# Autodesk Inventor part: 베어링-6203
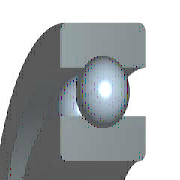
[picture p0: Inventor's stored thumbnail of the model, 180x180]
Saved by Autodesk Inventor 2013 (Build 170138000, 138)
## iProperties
IsCustomPart: 0
Created: 2016-05
Part Number: 베어링-6203
Material: 강철, 연강
Description: 깊은 그루브 볼 베어링
Document SubType Name: Modeling
Standard: KS B 2023
Designer: mduedu
Standards Organization: KS
Language: ko-KR
Size Designation: 6203 - 17 x 40 x 12
Categories: <MemberInstance><Categories><Category DisplayName="샤프트 부품" InternalName="7f7aeb1f-a693-4053-b835-cee3144e0d98" Mnemonic="SHFT"><Category DisplayName="베어링" Inter
Density: 1 g/cm^3
Author: mduedu
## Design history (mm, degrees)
sketch "스케치" dims "d0" = 5.98 (= -0.26 x WD + 0.26 x BD)
  geometry: L1 (3.01, 14.25)-(8.99, 14.25); L2 (6, 14.25)-(6, 11.26); L3 (6, 14.25)-(6, 17.24); L4 (3.778, 12.249)-(0, 12.249); L5 (0, 8.5)-(12, 8.5); L6 (3.778, 16.251)-(0, 16.251); L7 (0, 20)-(12, 20); L8 (12, 8.5)-(12, 12.249); L9 (8.222, 12.249)-(12, 12.249); L10 (8.222, 16.251)-(12, 16.251); L11 (12, 20)-(12, 16.251); L12 (-1.4, 0)-(8.4, 0) reference; L13 (0, -0.3)-(0, 5.3) reference
  constraints: 22 end point, 4 point on line, 2 collinear, 2 perpendicular, 2 symmetric about line, 1 midpoint, 1 parallel, 14 other
  dimensions: "d9" = 17 diameter of L5 L12 (= WD); "d11" = 40 diameter of L7 L12 (= BD); "d12" = 12 distance between parallel lines of L8 L13 (= KB); "d13" = 24.498 diameter of L9 L12 (= 0.326 x BD + 0.674 x WD)
revolve "본체" stored, may be unused: angle "d6" = 90 deg
revolve "볼" stored, may be unused: angle "d7" = 90 deg
pattern_circular "IDS_ARRAYBALL[SIMPL:T]" dims angle "d3" = 360 deg
body "Solid1"
fillet "모깎기1" dims "d1" = 0.6 (= KRS)
other parameters: "WD" = 17 [user parameter; used in 5 equation terms], "BD" = 40 [user parameter; used in 5 equation terms], "KB" = 12 [user parameter; used in 1 equation term], "KRS" = 0.6 [user parameter; used in 1 equation term], "d4" = 0, "d5" = 0, "d8" = 0, "d14" = 0, "d15" = 0, "BBA" = 0 [user parameter], "BC0" = 4750000 [user parameter], "BC" = 9560000 [user parameter], "WR" = 8.5 (= 0.5 x WD) [user parameter]
